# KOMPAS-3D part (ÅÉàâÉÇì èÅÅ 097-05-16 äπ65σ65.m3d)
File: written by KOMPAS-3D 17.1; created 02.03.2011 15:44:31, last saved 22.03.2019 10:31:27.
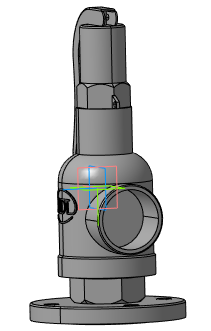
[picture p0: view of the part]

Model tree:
1. Плоскость XY
2. Плоскость ZX
3. Плоскость ZY
4. Ось X
5. Ось Y
6. Ось Z
7. Начало координат
8. Операция без истории:2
